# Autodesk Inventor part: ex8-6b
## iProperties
Author: J. DESIGNER
Created: 2001-10
Part Number: ex8-6b
Document SubType Name: Modeling
Designer: J. DESIGNER
Control State: 0
Master: False
Checked Out: False
PropertySet Name: Design Tracking Control
Shininess: 20.0
Angle Display Precision: 2
Document Length Units: 11272
Document Angle Units: 11286
Document Time Units: 11279
Document Mass Units: 11290
Document Length Units Precision: 3
Document Angle Units Precision: 2
Compacted: False
PropertySet Name: _Private Model Information
Density: 0.0
Volumn: 0.0
Area: 0.0
PropertySet Name: Model Information
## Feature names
1. Derived Body1 [Tagging]
